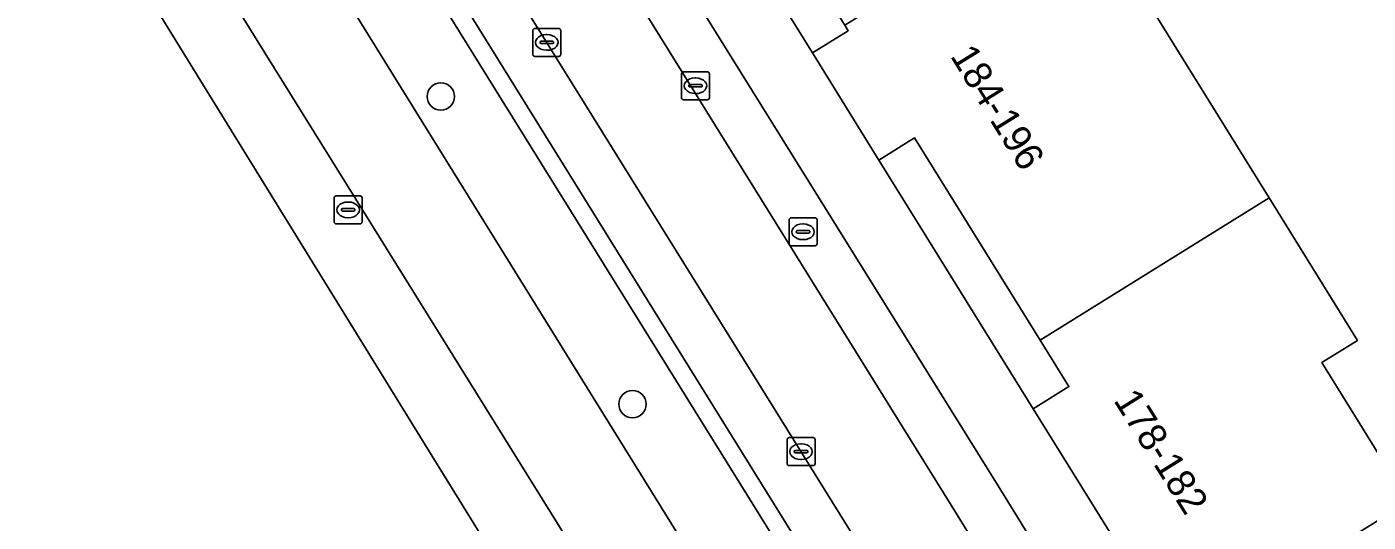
# Model space of a CAD drawing. Extents: x 160377 to 161131, y 383938 to 384853.
# Drawn here: x 160642.57 to 160690.47, y 384283.03 to 384300.7 of the extents above; entities that cross this region are included whole.
import ezdxf

# ---------------------------------------------------------------- set-up
doc = ezdxf.new("R2010")
doc.units = 0
for name, color, linetype in [('IMGEO_Berm_groen', 7, 'Continuous'), ('IMGEO_Berm_open', 7, 'Continuous'), ('IMGEO_Boom', 7, 'Continuous'), ('IMGEO_Erf', 7, 'Continuous'), ('IMGEO_Kolk', 7, 'Continuous'), ('IMGEO_Pand', 7, 'Continuous'), ('IMGEO_Pand_nummerreeks', 7, 'Continuous'), ('IMGEO_Parkeervlak_open', 7, 'Continuous'), ('IMGEO_Rijbaan_lokaal_gesloten', 7, 'Continuous'), ('IMGEO_Rijbaan_lokaal_open', 7, 'Continuous'), ('IMGEO_Rioolput', 7, 'Continuous'), ('IMGEO_Voetpad_open', 7, 'Continuous')]:
    doc.layers.add(name, color=color, linetype=linetype)

msp = doc.modelspace()

# ---------------------------------------------------------------- linework, layer by layer
at = {"layer": 'IMGEO_Berm_groen'}
msp.add_lwpolyline([(160723.217, 384195.887), (160717.726, 384204.774), (160689.782, 384250), (160684.931, 384257.851), (160678.757, 384267.157), (160643.611, 384323.728), (160641.325, 384327.654), (160641.221, 384327.588), (160638.839, 384326.083), (160668.175, 384278.809), (160686.009, 384250), (160707.361, 384215.678), (160725.992, 384185.588), (160730.335, 384178.88)], dxfattribs=at)
at = {"layer": 'IMGEO_Berm_open'}
msp.add_lwpolyline([(160644.163, 384324.071), (160643.611, 384323.728), (160678.757, 384267.157), (160679.306, 384267.498)], close=True, dxfattribs=at)
at = {"layer": 'IMGEO_Boom'}
for centre in [(160657.355, 384298.215), (160664.198, 384287.237)]:
    msp.add_circle(centre, 0.489, dxfattribs=at)
at = {"layer": 'IMGEO_Erf'}
msp.add_lwpolyline([(160693.226, 384305.58), (160689.988, 384303.573), (160687.512, 384307.568), (160681.282, 384303.706), (160686.93, 384294.596), (160690.082, 384289.513), (160688.808, 384288.723), (160691.891, 384283.749)], dxfattribs=at)
at = {"layer": 'IMGEO_Kolk'}
for p, q in [((160660.637, 384299.719), (160660.637, 384300.571)), ((160660.712, 384300.645), (160661.564, 384300.645)), ((160661.638, 384300.571), (160661.638, 384299.719)), ((160660.896, 384300.139), (160660.896, 384300.151)), ((160661.334, 384300.102), (160660.936, 384300.102)), ((160660.939, 384300.188), (160661.337, 384300.188)), ((160661.125, 384300.425), (160661.15, 384300.425)), ((160661.38, 384300.151), (160661.38, 384300.139)), ((160661.564, 384299.645), (160660.712, 384299.645)), ((160661.148, 384299.865), (160661.123, 384299.865)), ((160666.021, 384299.099), (160666.873, 384299.099)), ((160665.946, 384298.173), (160665.946, 384299.025)), ((160666.205, 384298.593), (160666.205, 384298.605)), ((160666.248, 384298.642), (160666.646, 384298.642)), ((160666.434, 384298.879), (160666.459, 384298.879)), ((160666.689, 384298.605), (160666.689, 384298.593)), ((160666.947, 384299.025), (160666.947, 384298.173)), ((160666.643, 384298.556), (160666.245, 384298.556)), ((160666.457, 384298.319), (160666.432, 384298.319)), ((160666.873, 384298.099), (160666.021, 384298.099)), ((160669.717, 384285.119), (160669.717, 384285.971)), ((160669.792, 384286.045), (160670.644, 384286.045)), ((160670.205, 384285.825), (160670.23, 384285.825)), ((160670.718, 384285.971), (160670.718, 384285.119)), ((160669.976, 384285.539), (160669.976, 384285.551)), ((160670.414, 384285.502), (160670.016, 384285.502)), ((160670.019, 384285.588), (160670.417, 384285.588)), ((160670.228, 384285.265), (160670.203, 384285.265)), ((160670.46, 384285.551), (160670.46, 384285.539)), ((160670.644, 384285.045), (160669.792, 384285.045))]:
    msp.add_line(p, q, dxfattribs=at)
for points in [[(160660.637, 384299.719), (160660.637, 384300.571)], [(160660.712, 384300.645), (160661.564, 384300.645)], [(160661.638, 384300.571), (160661.638, 384299.719)], [(160661.564, 384299.645), (160660.712, 384299.645)], [(160666.021, 384299.099), (160666.873, 384299.099)], [(160665.946, 384298.173), (160665.946, 384299.025)], [(160666.947, 384299.025), (160666.947, 384298.173)], [(160666.873, 384298.099), (160666.021, 384298.099)], [(160669.717, 384285.119), (160669.717, 384285.971)], [(160669.792, 384286.045), (160670.644, 384286.045)], [(160670.718, 384285.971), (160670.718, 384285.119)], [(160670.644, 384285.045), (160669.792, 384285.045)]]:
    msp.add_lwpolyline(points, dxfattribs=at)
for centre, radius, start, end in [((160660.714, 384300.569), 0.0765, 91.552, 178.448), ((160660.714, 384300.569), 0.0765, 91.552, 178.448), ((160661.562, 384300.569), 0.0765, 1.552, 88.448), ((160661.562, 384300.569), 0.0765, 1.552, 88.448), ((160660.936, 384300.148), 0.0403, 85.8775, 175.7526), ((160660.933, 384300.138), 0.0366, 178.938, 274.7102), ((160661.337, 384300.145), 0.043, 264.8664, 352.4533), ((160661.341, 384300.15), 0.0386, 1.7309, 96.639), ((160660.714, 384299.721), 0.0765, 181.552, 268.448), ((160660.714, 384299.721), 0.0765, 181.552, 268.448), ((160661.562, 384299.721), 0.0765, 271.552, 358.448), ((160661.562, 384299.721), 0.0765, 271.552, 358.448), ((160666.023, 384299.023), 0.0765, 91.552, 178.448), ((160666.023, 384299.023), 0.0765, 91.552, 178.448), ((160666.871, 384299.023), 0.0765, 1.552, 88.448), ((160666.871, 384299.023), 0.0765, 1.552, 88.448), ((160666.245, 384298.602), 0.0403, 85.8775, 175.7526), ((160666.65, 384298.604), 0.0386, 1.7309, 96.639), ((160666.023, 384298.175), 0.0765, 181.552, 268.448), ((160666.023, 384298.175), 0.0765, 181.552, 268.448), ((160666.242, 384298.592), 0.0366, 178.938, 274.7102), ((160666.646, 384298.599), 0.043, 264.8664, 352.4533), ((160666.871, 384298.175), 0.0765, 271.552, 358.448), ((160666.871, 384298.175), 0.0765, 271.552, 358.448), ((160669.794, 384285.969), 0.0765, 91.552, 178.448), ((160669.794, 384285.969), 0.0765, 91.552, 178.448), ((160670.642, 384285.969), 0.0765, 1.552, 88.448), ((160670.642, 384285.969), 0.0765, 1.552, 88.448), ((160670.016, 384285.548), 0.0403, 85.8775, 175.7526), ((160670.013, 384285.538), 0.0366, 178.938, 274.7102), ((160670.417, 384285.545), 0.043, 264.8664, 352.4533), ((160670.421, 384285.55), 0.0386, 1.7309, 96.639), ((160669.794, 384285.121), 0.0765, 181.552, 268.448), ((160669.794, 384285.121), 0.0765, 181.552, 268.448), ((160670.642, 384285.121), 0.0765, 271.552, 358.448), ((160670.642, 384285.121), 0.0765, 271.552, 358.448)]:
    msp.add_arc(centre, radius, start, end, dxfattribs=at)
for centre, major_axis, ratio, start_param, end_param in [((160661.124, 384300.145), (-0.387, 0.002), 0.722429, 4.712389, 7.853982), ((160661.149, 384300.145), (-0.39, 0.002), 0.717154, 1.570796, 4.712389), ((160666.433, 384298.599), (-0.387, 0.002), 0.722429, 4.712389, 7.853982), ((160666.458, 384298.599), (-0.39, 0.002), 0.717154, 1.570796, 4.712389), ((160670.204, 384285.545), (-0.387, 0.002), 0.722429, 4.712389, 7.853982), ((160670.229, 384285.545), (-0.39, 0.002), 0.717154, 1.570796, 4.712389)]:
    msp.add_ellipse(centre, major_axis=major_axis, ratio=ratio, start_param=start_param, end_param=end_param, dxfattribs=at)
at = {"layer": 'IMGEO_Pand'}
for points in [[(160681.282, 384303.706), (160687.512, 384307.568), (160689.988, 384303.573), (160693.226, 384305.58), (160689.416, 384311.726), (160679.992, 384305.865), (160676.071, 384303.426), (160671.781, 384300.758), (160671.904, 384300.56), (160670.629, 384299.77), (160672.997, 384295.946), (160674.272, 384296.736), (160678.76, 384289.516), (160686.93, 384294.596)], [(160688.808, 384288.723), (160690.082, 384289.513), (160686.93, 384294.596), (160678.76, 384289.516), (160679.784, 384287.867), (160678.51, 384287.076), (160683.721, 384278.684), (160691.891, 384283.749)]]:
    msp.add_lwpolyline(points, close=True, dxfattribs=at)
at = {"layer": 'IMGEO_Parkeervlak_open'}
for points in [[(160682.805, 384265.309), (160644.178, 384327.417)], [(160644.074, 384324.214), (160644.163, 384324.071), (160679.306, 384267.498), (160679.333, 384267.455)], [(160650.494, 384323.988), (160675.793, 384283.293), (160681.886, 384273.43)], [(160682.007, 384276.633), (160677.257, 384284.323), (160653.446, 384322.554)]]:
    msp.add_lwpolyline(points, dxfattribs=at)
at = {"layer": 'IMGEO_Rijbaan_lokaal_gesloten'}
for points in [[(160707.361, 384215.678), (160686.009, 384250), (160668.175, 384278.809), (160638.839, 384326.083), (160638.069, 384327.324), (160635.054, 384325.513), (160671.485, 384266.967), (160720.734, 384187.958), (160725.107, 384181.899), (160733.069, 384173.147), (160739.95, 384167.105)], [(160745.933, 384161.486), (160743.205, 384164.034), (160739.95, 384167.105), (160733.069, 384173.147), (160725.107, 384181.899), (160720.734, 384187.958), (160671.485, 384266.967), (160635.054, 384325.513), (160633.021, 384324.291), (160657.045, 384285.38), (160674.582, 384257.042), (160723.846, 384177.438), (160747.142, 384155.348), (160749.892, 384150.791)]]:
    msp.add_lwpolyline(points, dxfattribs=at)
at = {"layer": 'IMGEO_Rijbaan_lokaal_open'}
for points in [[(160643.349, 384328.933), (160644.178, 384327.417), (160682.805, 384265.309), (160690.325, 384258.727), (160695.745, 384250), (160728.731, 384197.046), (160731.01, 384193.377), (160731.116, 384193.207), (160731.945, 384191.378), (160732.201, 384190.814), (160739.253, 384175.262), (160741.715, 384169.832), (160744.863, 384171.28), (160744.459, 384172.157)], [(160683.033, 384271.719), (160681.886, 384273.43), (160675.793, 384283.293), (160650.494, 384323.988), (160647.934, 384328.323)]]:
    msp.add_lwpolyline(points, dxfattribs=at)
at = {"layer": 'IMGEO_Rioolput'}
for p, q in [((160653.544, 384293.745), (160653.544, 384294.597)), ((160653.619, 384294.671), (160654.471, 384294.671)), ((160654.032, 384294.451), (160654.057, 384294.451)), ((160654.545, 384294.597), (160654.545, 384293.745)), ((160653.803, 384294.165), (160653.803, 384294.177)), ((160654.241, 384294.128), (160653.843, 384294.128)), ((160653.846, 384294.214), (160654.244, 384294.214)), ((160654.055, 384293.891), (160654.03, 384293.891)), ((160654.287, 384294.177), (160654.287, 384294.165)), ((160669.789, 384292.962), (160669.789, 384293.814)), ((160669.864, 384293.888), (160670.716, 384293.888)), ((160670.79, 384293.814), (160670.79, 384292.962)), ((160654.471, 384293.671), (160653.619, 384293.671)), ((160670.048, 384293.382), (160670.048, 384293.394)), ((160670.486, 384293.345), (160670.088, 384293.345)), ((160670.091, 384293.431), (160670.489, 384293.431)), ((160670.277, 384293.668), (160670.302, 384293.668)), ((160670.532, 384293.394), (160670.532, 384293.382)), ((160670.716, 384292.888), (160669.864, 384292.888)), ((160670.3, 384293.108), (160670.275, 384293.108))]:
    msp.add_line(p, q, dxfattribs=at)
for points in [[(160653.544, 384293.745), (160653.544, 384294.597)], [(160653.619, 384294.671), (160654.471, 384294.671)], [(160654.545, 384294.597), (160654.545, 384293.745)], [(160669.789, 384292.962), (160669.789, 384293.814)], [(160669.864, 384293.888), (160670.716, 384293.888)], [(160670.79, 384293.814), (160670.79, 384292.962)], [(160654.471, 384293.671), (160653.619, 384293.671)], [(160670.716, 384292.888), (160669.864, 384292.888)]]:
    msp.add_lwpolyline(points, dxfattribs=at)
for centre, radius, start, end in [((160653.621, 384294.595), 0.0765, 91.552, 178.448), ((160653.621, 384294.595), 0.0765, 91.552, 178.448), ((160654.469, 384294.595), 0.0765, 1.552, 88.448), ((160654.469, 384294.595), 0.0765, 1.552, 88.448), ((160653.843, 384294.174), 0.0403, 85.8775, 175.7526), ((160653.84, 384294.164), 0.0366, 178.938, 274.7102), ((160654.244, 384294.171), 0.043, 264.8664, 352.4533), ((160654.248, 384294.176), 0.0386, 1.7309, 96.639), ((160669.866, 384293.812), 0.0765, 91.552, 178.448), ((160669.866, 384293.812), 0.0765, 91.552, 178.448), ((160670.714, 384293.812), 0.0765, 1.552, 88.448), ((160670.714, 384293.812), 0.0765, 1.552, 88.448), ((160653.621, 384293.747), 0.0765, 181.552, 268.448), ((160653.621, 384293.747), 0.0765, 181.552, 268.448), ((160654.469, 384293.747), 0.0765, 271.552, 358.448), ((160654.469, 384293.747), 0.0765, 271.552, 358.448), ((160670.088, 384293.391), 0.0403, 85.8775, 175.7526), ((160670.085, 384293.381), 0.0366, 178.938, 274.7102), ((160670.489, 384293.388), 0.043, 264.8664, 352.4533), ((160670.493, 384293.393), 0.0386, 1.7309, 96.639), ((160669.866, 384292.964), 0.0765, 181.552, 268.448), ((160669.866, 384292.964), 0.0765, 181.552, 268.448), ((160670.714, 384292.964), 0.0765, 271.552, 358.448), ((160670.714, 384292.964), 0.0765, 271.552, 358.448)]:
    msp.add_arc(centre, radius, start, end, dxfattribs=at)
for centre, major_axis, ratio, start_param, end_param in [((160654.031, 384294.171), (-0.387, 0.002), 0.722429, 4.712389, 7.853982), ((160654.056, 384294.171), (-0.39, 0.002), 0.717154, 1.570796, 4.712389), ((160670.276, 384293.388), (-0.387, 0.002), 0.722429, 4.712389, 7.853982), ((160670.301, 384293.388), (-0.39, 0.002), 0.717154, 1.570796, 4.712389)]:
    msp.add_ellipse(centre, major_axis=major_axis, ratio=ratio, start_param=start_param, end_param=end_param, dxfattribs=at)
at = {"layer": 'IMGEO_Voetpad_open'}
for points in [[(160653.446, 384322.554), (160677.257, 384284.323), (160682.007, 384276.633)], [(160684.156, 384270.615), (160688.37, 384267.426), (160689.017, 384267.824), (160690.096, 384268.487), (160688.162, 384271.533), (160683.721, 384278.684), (160678.51, 384287.076), (160672.997, 384295.946), (160670.629, 384299.77), (160667.313, 384305.099)]]:
    msp.add_lwpolyline(points, dxfattribs=at)
for points in [[(160670.393, 384302.989), (160668.588, 384305.889), (160667.313, 384305.099), (160670.629, 384299.77), (160671.904, 384300.56), (160671.781, 384300.758)], [(160672.997, 384295.946), (160678.51, 384287.076), (160679.784, 384287.867), (160678.76, 384289.516), (160674.272, 384296.736)]]:
    msp.add_lwpolyline(points, close=True, dxfattribs=at)

# ---------------------------------------------------------------- texts
at = {"layer": 'IMGEO_Pand_nummerreeks'}
for s, rotation, p in [('184-196', 301.776, (160675.523, 384299.665)), ('178-182', 302.0568, (160681.357, 384287.374))]:
    msp.add_text(s, height=1, rotation=rotation, dxfattribs=at).set_placement(p)

doc.saveas('drawing.dxf')
